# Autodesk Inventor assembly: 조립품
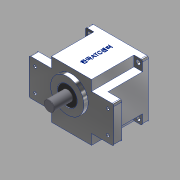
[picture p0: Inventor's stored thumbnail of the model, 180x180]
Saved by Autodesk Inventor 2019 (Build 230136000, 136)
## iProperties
Created: 2020-01
Part Number: 조립품
Material: 일반
Document SubType Name: Assembly
Designer: 323-3
Author: 323-3
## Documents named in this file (10)
- C:\Users\323-3\Desktop\700119V1002\조립품.iam
- C:\Users\323-3\Desktop\700119V1002\본체.ipt
- C:\Users\323-3\Desktop\700119V1002\커버.ipt
- C:\Users\323-3\Desktop\700119V1002\메인 축.ipt
- C:\Users\323-3\Desktop\700119V1002\서브 축.ipt
- C:\Users\323-3\Desktop\700119V1002\볼트 M4.ipt
- C:\Users\323-3\Desktop\700119V1002\베어링 6003.ipt
- C:\Users\323-3\Desktop\700119V1002\베어링 608.ipt
- C:\Users\323-3\Desktop\700119V1002\오일 실 17 32 8.ipt
- C:\Users\323-3\Desktop\700119V1002\오일 실 8 22 7.ipt
